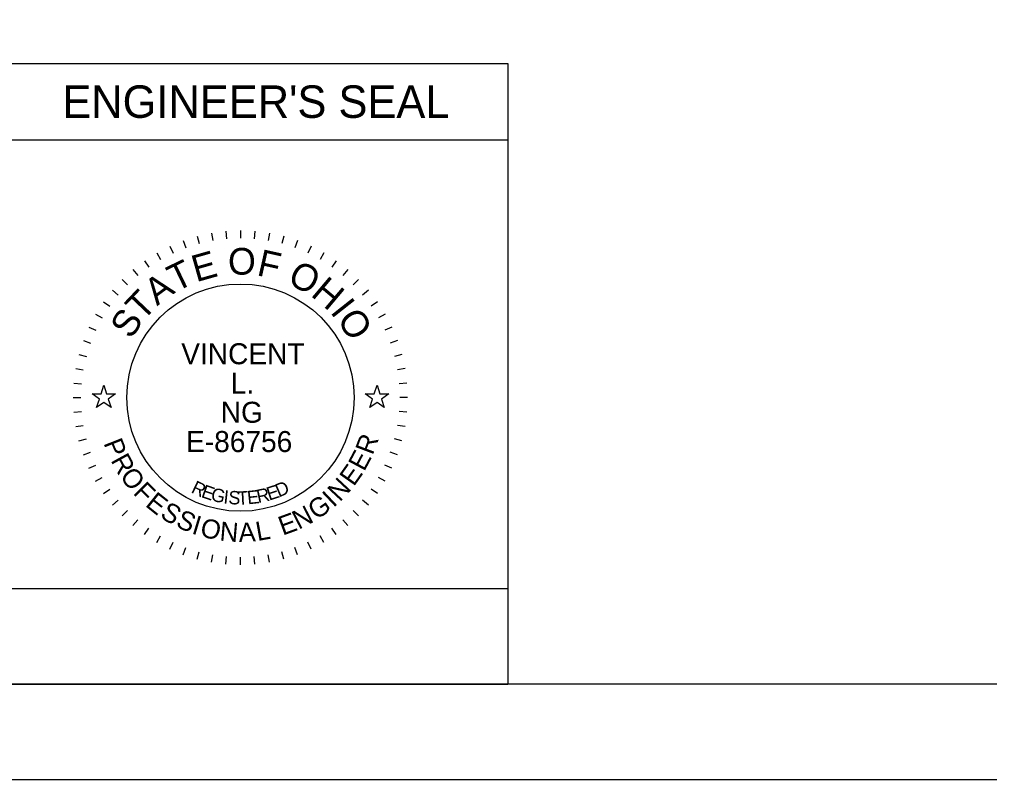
# Model space of a CAD drawing. Extents: x 0 to 42.4, y 0 to 22.
# Drawn here: x 23.84 to 28.92, y 0 to 3.98 of the extents above; entities that cross this region are included whole.
import ezdxf

# ---------------------------------------------------------------- set-up
doc = ezdxf.new("R2010")
doc.units = 0
for name, color, linetype in [('SH_Border', 7, 'Continuous'), ('SH_Cut_Line', 7, 'Continuous'), ('SH_Data', 7, 'Continuous'), ('SH_Seal', 7, 'Continuous')]:
    doc.layers.add(name, color=color, linetype=linetype)

msp = doc.modelspace()

# ---------------------------------------------------------------- linework, layer by layer
at = {"layer": 'SH_Border'}
msp.add_lwpolyline([(1.5, 21.5), (33.5, 21.5), (33.5, 0.5), (1.5, 0.5)], close=True, dxfattribs=at)
at = {"layer": 'SH_Cut_Line'}
msp.add_lwpolyline([(0, 0), (34, 0), (34, 22), (0, 22)], close=True, dxfattribs=at)
at = {"layer": 'SH_Data'}
for p, q in [((23.6, 3.75), (26.4, 3.75)), ((26.4, 3.75), (26.4, 0.5)), ((23.6, 3.35), (26.4, 3.35)), ((23.6, 0.5), (26.4, 0.5))]:
    msp.add_line(p, q, dxfattribs=at)
msp.add_lwpolyline([(23.6, 0.5), (23.6, 1), (26.4, 1), (26.4, 0.5)], close=True, dxfattribs=at)
at = {"layer": 'SH_Seal'}
for p, q in [((24.7735, 2.8452), (24.7839, 2.8065)), ((24.8481, 2.8617), (24.855, 2.8223)), ((24.9237, 2.8717), (24.9272, 2.8318)), ((25, 2.875), (25, 2.835)), ((25.0763, 2.8717), (25.0728, 2.8318)), ((25.1519, 2.8617), (25.145, 2.8223)), ((25.2265, 2.8452), (25.2161, 2.8065)), ((24.7007, 2.8222), (24.7144, 2.7846)), ((25.2993, 2.8222), (25.2856, 2.7846)), ((24.5625, 2.7578), (24.5825, 2.7231)), ((24.6302, 2.793), (24.6471, 2.7568)), ((25.3698, 2.793), (25.3529, 2.7568)), ((25.4375, 2.7578), (25.4175, 2.7231)), ((24.4981, 2.7168), (24.5211, 2.684)), ((25.5019, 2.7168), (25.4789, 2.684)), ((24.4376, 2.6703), (24.4633, 2.6396)), ((25.5624, 2.6703), (25.5367, 2.6396)), ((24.3813, 2.6187), (24.4096, 2.5904)), ((25.6187, 2.6187), (25.5904, 2.5904)), ((24.3297, 2.5624), (24.3604, 2.5367)), ((25.6703, 2.5624), (25.6396, 2.5367)), ((24.2832, 2.5019), (24.316, 2.4789)), ((25.7168, 2.5019), (25.684, 2.4789)), ((24.2422, 2.4375), (24.2769, 2.4175)), ((25.7578, 2.4375), (25.7231, 2.4175)), ((24.207, 2.3698), (24.2432, 2.3529)), ((25.793, 2.3698), (25.7568, 2.3529)), ((24.1778, 2.2993), (24.2154, 2.2856)), ((25.8222, 2.2993), (25.7846, 2.2856)), ((24.1548, 2.2265), (24.1935, 2.2161)), ((25.8452, 2.2265), (25.8065, 2.2161)), ((24.1383, 2.1519), (24.1777, 2.145)), ((25.8617, 2.1519), (25.8223, 2.145)), ((24.1283, 2.0763), (24.1682, 2.0728)), ((25.8717, 2.0763), (25.8318, 2.0728)), ((24.125, 2), (24.165, 2)), ((25.875, 2), (25.835, 2)), ((24.1283, 1.9237), (24.1682, 1.9272)), ((25.8717, 1.9237), (25.8318, 1.9272)), ((24.1383, 1.8481), (24.1777, 1.855)), ((25.8617, 1.8481), (25.8223, 1.855)), ((24.1548, 1.7735), (24.1935, 1.7839)), ((25.8452, 1.7735), (25.8065, 1.7839)), ((24.1778, 1.7007), (24.2154, 1.7144)), ((25.8222, 1.7007), (25.7846, 1.7144)), ((24.207, 1.6302), (24.2432, 1.6471)), ((25.793, 1.6302), (25.7568, 1.6471)), ((24.2422, 1.5625), (24.2769, 1.5825)), ((25.7578, 1.5625), (25.7231, 1.5825)), ((24.2832, 1.4981), (24.316, 1.5211)), ((25.7168, 1.4981), (25.684, 1.5211)), ((24.3297, 1.4376), (24.3604, 1.4633)), ((25.6703, 1.4376), (25.6396, 1.4633)), ((24.3813, 1.3813), (24.4096, 1.4096)), ((25.6187, 1.3813), (25.5904, 1.4096)), ((24.4376, 1.3297), (24.4633, 1.3604)), ((25.5624, 1.3297), (25.5367, 1.3604)), ((24.4981, 1.2832), (24.5211, 1.316)), ((24.5625, 1.2422), (24.5825, 1.2769)), ((25.4375, 1.2422), (25.4175, 1.2769)), ((25.5019, 1.2832), (25.4789, 1.316)), ((24.6302, 1.207), (24.6471, 1.2432)), ((25.3698, 1.207), (25.3529, 1.2432)), ((24.7007, 1.1778), (24.7144, 1.2154)), ((24.7735, 1.1548), (24.7839, 1.1935)), ((24.8481, 1.1383), (24.855, 1.1777)), ((24.9237, 1.1283), (24.9272, 1.1682)), ((25.0763, 1.1283), (25.0728, 1.1682)), ((25.1519, 1.1383), (25.145, 1.1777)), ((25.2265, 1.1548), (25.2161, 1.1935)), ((25.2993, 1.1778), (25.2856, 1.2154)), ((25, 1.125), (25, 1.165))]:
    msp.add_line(p, q, dxfattribs=at)
for points in [[(24.2236, 2.02), (24.2705, 2.02), (24.285, 2.0645), (24.2995, 2.02), (24.3464, 2.02), (24.3085, 1.9924), (24.323, 1.9478), (24.285, 1.9754), (24.247, 1.9478), (24.2615, 1.9924)], [(25.6536, 2.02), (25.7005, 2.02), (25.715, 2.0645), (25.7295, 2.02), (25.7764, 2.02), (25.7385, 1.9924), (25.753, 1.9478), (25.715, 1.9754), (25.677, 1.9478), (25.6915, 1.9924)]]:
    msp.add_lwpolyline(points, close=True, dxfattribs=at)
msp.add_circle((25, 2), 0.595, dxfattribs=at)

# ---------------------------------------------------------------- texts
at = {"layer": 'SH_Data'}
msp.add_text("ENGINEER'S SEAL", height=0.17, dxfattribs=at).set_placement((24.0676, 3.465))
at = {"layer": 'SH_Seal'}
for s, height, rotation, p in [('E', 0.14, 15.7571, (24.7684, 2.6038)), ('O', 0.14, 359.7812, (24.9347, 2.6443)), ('F', 0.14, 347.4362, (25.0811, 2.6417)), ('T', 0.14, 25.7167, (24.6616, 2.5518)), ('O', 0.14, 332.2586, (25.2398, 2.6015)), ('A', 0.14, 36.4747, (24.5634, 2.4781)), ('H', 0.14, 319.9136, (25.3632, 2.5361)), ('T', 0.14, 46.4344, (24.4883, 2.3964)), ('I', 0.14, 308.367, (25.4665, 2.4483)), ('S', 0.14, 57.1924, (24.4281, 2.3014)), ('O', 0.14, 303.1491, (25.5021, 2.4089)), ('P', 0.1, 291.494, (24.2823, 1.7621)), ('R', 0.1, 69.2322, (25.6919, 1.6954)), ('E', 0.1, 61.9951, (25.6476, 1.6098)), ('R', 0.1, 298.7311, (24.319, 1.6717)), ('O', 0.1, 306.4666, (24.3655, 1.5883)), ('E', 0.1, 54.758, (25.5933, 1.5314)), ('N', 0.1, 47.0224, (25.5202, 1.4508)), ('F', 0.1, 314.7068, (24.4343, 1.4983)), ('R', 0.07, 334.487, (24.7375, 1.5051)), ('E', 0.07, 341.04, (24.7906, 1.4801)), ('G', 0.07, 347.4752, (24.8414, 1.4618)), ('R', 0.07, 11.9184, (25.0925, 1.4474)), ('E', 0.07, 17.6836, (25.1498, 1.4602)), ('D', 0.07, 23.3052, (25.201, 1.477)), ('E', 0.1, 321.4393, (24.4978, 1.4348)), ('I', 0.07, 353.7858, (24.9091, 1.4468)), ('S', 0.07, 356.8926, (24.9358, 1.4429)), ('T', 0.07, 3.0061, (24.9857, 1.4387)), ('E', 0.07, 6.0117, (25.0389, 1.4412)), ('G', 0.1, 35.0469, (25.3981, 1.357)), ('I', 0.1, 43.287, (25.4868, 1.4214)), ('S', 0.1, 328.6764, (24.5743, 1.3752)), ('N', 0.1, 27.3113, (25.3045, 1.3075)), ('S', 0.1, 335.9134, (24.6564, 1.3266)), ('I', 0.1, 343.1505, (24.7406, 1.2897)), ('E', 0.1, 20.0742, (25.2212, 1.277)), ('O', 0.1, 346.8859, (24.7839, 1.2751)), ('N', 0.1, 355.1261, (24.8888, 1.2517)), ('A', 0.1, 2.8617, (24.9923, 1.2437)), ('L', 0.1, 10.0987, (25.0894, 1.249))]:
    msp.add_text(s, height=height, rotation=rotation, dxfattribs=at).set_placement(p)
for s, p in [('VINCENT', (24.6902, 2.1749)), ('L.', (24.9495, 2.0216)), ('NG', (24.8971, 1.8684)), ('E-86756', (24.7154, 1.7151))]:
    msp.add_text(s, height=0.11, dxfattribs=at).set_placement(p)

doc.saveas('drawing.dxf')
